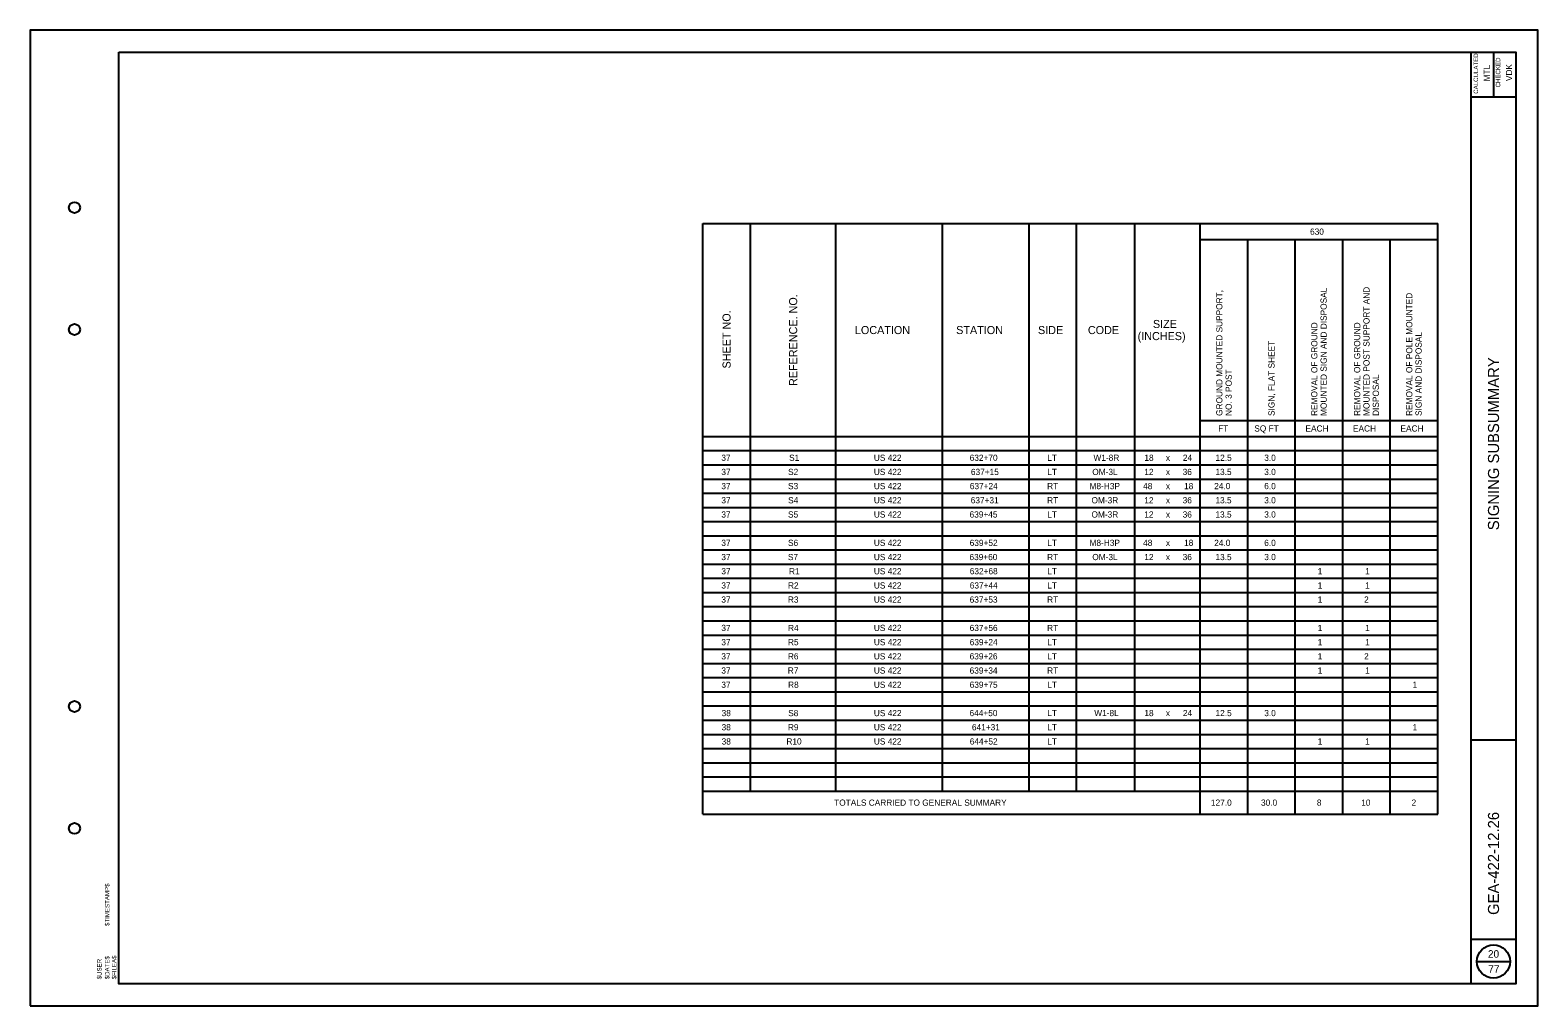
# Model space of a CAD drawing. Extents: x 0 to 34, y 0 to 22.
import ezdxf

# ---------------------------------------------------------------- set-up
doc = ezdxf.new("R2010")
doc.units = 0
for name, color, linetype in [('SH_Border', 7, 'Continuous'), ('SH_Cut_Line', 7, 'Continuous'), ('SH_Data', 7, 'Continuous'), ('SH_Text', 7, 'Continuous')]:
    doc.layers.add(name, color=color, linetype=linetype)

msp = doc.modelspace()

# ---------------------------------------------------------------- linework, layer by layer
at = {"layer": 'SH_Border'}
for p, q in [((32.5, 0.5), (32.5, 21.5)), ((33, 21.5), (33, 20.5)), ((32.5, 20.5), (33.5, 20.5)), ((32.5, 6), (33.5, 6)), ((32.5, 1.5), (33.5, 1.5))]:
    msp.add_line(p, q, dxfattribs=at)
msp.add_lwpolyline([(2, 21.5), (33.5, 21.5), (33.5, 0.5), (2, 0.5)], close=True, dxfattribs=at)
for centre in [(1, 18), (1, 15.25), (1, 6.75), (1, 4)]:
    msp.add_circle(centre, 0.125, dxfattribs=at)
at = {"layer": 'SH_Cut_Line'}
msp.add_lwpolyline([(0, 0), (34, 0), (34, 22), (0, 22)], close=True, dxfattribs=at)
at = {"layer": 'SH_Data'}
msp.add_line((32.625, 1), (33.375, 1), dxfattribs=at)
msp.add_circle((33, 1), 0.375, dxfattribs=at)
at = {"layer": 'SH_Text'}
for p, q in [((15.17, 17.637), (15.17, 17.637)), ((15.17, 17.637), (31.741, 17.637)), ((15.17, 4.323), (15.17, 17.637)), ((16.241, 4.842), (16.241, 17.637)), ((18.172, 4.842), (18.172, 17.637)), ((20.577, 4.842), (20.577, 17.637)), ((22.525, 4.842), (22.525, 17.637)), ((23.596, 4.842), (23.596, 17.637)), ((24.912, 4.842), (24.912, 17.637)), ((26.387, 4.323), (26.387, 17.637)), ((31.741, 4.323), (31.741, 17.637)), ((26.387, 17.277), (31.741, 17.277)), ((27.458, 4.323), (27.458, 17.277)), ((28.528, 4.323), (28.528, 17.277)), ((29.599, 4.323), (29.599, 17.277)), ((30.67, 4.323), (30.67, 17.277)), ((26.387, 13.199), (31.741, 13.199)), ((15.17, 12.839), (31.741, 12.839)), ((15.17, 12.519), (31.741, 12.519)), ((15.17, 12.199), (31.741, 12.199)), ((15.17, 11.879), (31.741, 11.879)), ((15.17, 11.56), (31.741, 11.56)), ((15.17, 11.24), (31.741, 11.24)), ((15.17, 10.92), (31.741, 10.92)), ((15.17, 10.6), (31.741, 10.6)), ((15.17, 10.28), (31.741, 10.28)), ((15.17, 9.96), (31.741, 9.96)), ((15.17, 9.64), (31.741, 9.64)), ((15.17, 9.32), (31.741, 9.32)), ((15.17, 9.001), (31.741, 9.001)), ((15.17, 8.681), (31.741, 8.681)), ((15.17, 8.361), (31.741, 8.361)), ((15.17, 8.041), (31.741, 8.041)), ((15.17, 7.721), (31.741, 7.721)), ((15.17, 7.401), (31.741, 7.401)), ((15.17, 7.081), (31.741, 7.081)), ((15.17, 6.762), (31.741, 6.762)), ((15.17, 6.442), (31.741, 6.442)), ((15.17, 6.122), (31.741, 6.122)), ((15.17, 5.802), (31.741, 5.802)), ((15.17, 5.482), (31.741, 5.482)), ((15.17, 5.162), (31.741, 5.162)), ((15.17, 4.842), (31.741, 4.842)), ((15.17, 4.323), (31.741, 4.323))]:
    msp.add_line(p, q, dxfattribs=at)

# ---------------------------------------------------------------- texts
at = {"layer": 'SH_Data'}
for s, height, rotation, p in [('CALCULATED', 0.1, 90, (32.652, 20.565)), ('MTL', 0.14, 90, (32.92, 20.844)), ('CHECKED', 0.1, 90, (33.152, 20.708)), ('VDK', 0.14, 90, (33.42, 20.851)), ('SIGNING SUBSUMMARY', 0.25, 90, (33.125, 10.724)), (' GEA-422-12.26 ', 0.25, 90, (33.125, 1.957)), ('$TIMESTAMP$', 0.1, 89.9931, (1.788, 1.8)), ('$USER', 0.1, 89.9931, (1.611, 0.598)), ('$DATE$', 0.1, 89.9931, (1.788, 0.598)), ('$FILEA$', 0.1, 89.9931, (1.944, 0.598))]:
    msp.add_text(s, height=height, rotation=rotation, dxfattribs=at).set_placement(p)
for s, p in [('20', (32.874, 1.085)), ('77', (32.882, 0.745))]:
    msp.add_text(s, height=0.17, dxfattribs=at).set_placement(p)
at = {"layer": 'SH_Text'}
for s, height, p in [('630', 0.14, (28.863, 17.387)), ('LOCATION', 0.182, (18.599, 15.147)), ('STATION', 0.182, (20.883, 15.147)), ('SIDE', 0.182, (22.728, 15.147)), ('CODE', 0.182, (23.853, 15.147)), ('SIZE', 0.182, (25.32, 15.284)), ('(INCHES)', 0.182, (24.975, 15.011)), ('FT', 0.14, (26.791, 12.949)), ('SQ FT', 0.14, (27.606, 12.949)), ('EACH', 0.14, (28.76, 12.949)), ('EACH', 0.14, (29.831, 12.949)), ('EACH', 0.14, (30.902, 12.949)), ('37', 0.14, (15.587, 12.289)), ('S1', 0.14, (17.115, 12.289)), ('US 422', 0.14, (19.026, 12.289)), ('632+70', 0.14, (21.187, 12.289)), ('LT', 0.14, (22.938, 12.289)), ('W1-8R', 0.14, (23.979, 12.289)), ('18', 0.14, (25.127, 12.289)), ('x', 0.14, (25.612, 12.289)), ('24', 0.14, (25.995, 12.289)), ('12.5', 0.14, (26.731, 12.289)), ('3.0', 0.14, (27.83, 12.289)), ('37', 0.14, (15.587, 11.969)), ('S2', 0.14, (17.092, 11.969)), ('US 422', 0.14, (19.026, 11.969)), ('637+15', 0.14, (21.215, 11.969)), ('LT', 0.14, (22.938, 11.969)), ('OM-3L', 0.14, (23.952, 11.969)), ('12', 0.14, (25.125, 11.969)), ('x', 0.14, (25.612, 11.969)), ('36', 0.14, (25.99, 11.969)), ('13.5', 0.14, (26.729, 11.969)), ('3.0', 0.14, (27.83, 11.969)), ('37', 0.14, (15.587, 11.65)), ('S3', 0.14, (17.091, 11.65)), ('US 422', 0.14, (19.026, 11.65)), ('637+24', 0.14, (21.19, 11.65)), ('RT', 0.14, (22.934, 11.65)), ('M8-H3P', 0.14, (23.89, 11.65)), ('48', 0.14, (25.099, 11.65)), ('x', 0.14, (25.612, 11.65)), ('18', 0.14, (26.022, 11.65)), ('24.0', 0.14, (26.701, 11.65)), ('6.0', 0.14, (27.83, 11.65)), ('37', 0.14, (15.587, 11.33)), ('S4', 0.14, (17.093, 11.33)), ('US 422', 0.14, (19.026, 11.33)), ('637+31', 0.14, (21.211, 11.33)), ('RT', 0.14, (22.934, 11.33)), ('OM-3R', 0.14, (23.934, 11.33)), ('12', 0.14, (25.125, 11.33)), ('x', 0.14, (25.612, 11.33)), ('36', 0.14, (25.99, 11.33)), ('13.5', 0.14, (26.729, 11.33)), ('3.0', 0.14, (27.83, 11.33)), ('37', 0.14, (15.587, 11.01)), ('S5', 0.14, (17.091, 11.01)), ('US 422', 0.14, (19.026, 11.01)), ('639+45', 0.14, (21.185, 11.01)), ('LT', 0.14, (22.938, 11.01)), ('OM-3R', 0.14, (23.934, 11.01)), ('12', 0.14, (25.125, 11.01)), ('x', 0.14, (25.612, 11.01)), ('36', 0.14, (25.99, 11.01)), ('13.5', 0.14, (26.729, 11.01)), ('3.0', 0.14, (27.83, 11.01)), ('37', 0.14, (15.587, 10.37)), ('S6', 0.14, (17.091, 10.37)), ('US 422', 0.14, (19.026, 10.37)), ('639+52', 0.14, (21.187, 10.37)), ('LT', 0.14, (22.938, 10.37)), ('M8-H3P', 0.14, (23.89, 10.37)), ('48', 0.14, (25.099, 10.37)), ('x', 0.14, (25.612, 10.37)), ('18', 0.14, (26.022, 10.37)), ('24.0', 0.14, (26.701, 10.37)), ('6.0', 0.14, (27.83, 10.37)), ('37', 0.14, (15.587, 10.05)), ('37', 0.14, (15.587, 9.73)), ('S7', 0.14, (17.088, 10.05)), ('R1', 0.14, (17.113, 9.73)), ('US 422', 0.14, (19.026, 10.05)), ('US 422', 0.14, (19.026, 9.73)), ('639+60', 0.14, (21.182, 10.05)), ('632+68', 0.14, (21.189, 9.73)), ('RT', 0.14, (22.934, 10.05)), ('LT', 0.14, (22.938, 9.73)), ('OM-3L', 0.14, (23.952, 10.05)), ('12', 0.14, (25.125, 10.05)), ('x', 0.14, (25.612, 10.05)), ('36', 0.14, (25.99, 10.05)), ('13.5', 0.14, (26.729, 10.05)), ('3.0', 0.14, (27.83, 10.05)), ('1', 0.14, (29.035, 9.73)), ('1', 0.14, (30.105, 9.73)), ('37', 0.14, (15.587, 9.41)), ('R2', 0.14, (17.09, 9.41)), ('US 422', 0.14, (19.026, 9.41)), ('637+44', 0.14, (21.189, 9.41)), ('LT', 0.14, (22.938, 9.41)), ('1', 0.14, (29.035, 9.41)), ('1', 0.14, (30.105, 9.41)), ('37', 0.14, (15.587, 9.091)), ('R3', 0.14, (17.088, 9.091)), ('US 422', 0.14, (19.026, 9.091)), ('637+53', 0.14, (21.187, 9.091)), ('RT', 0.14, (22.934, 9.091)), ('1', 0.14, (29.035, 9.091)), ('2', 0.14, (30.082, 9.091)), ('37', 0.14, (15.587, 8.451)), ('R4', 0.14, (17.091, 8.451)), ('US 422', 0.14, (19.026, 8.451)), ('637+56', 0.14, (21.187, 8.451)), ('RT', 0.14, (22.934, 8.451)), ('1', 0.14, (29.035, 8.451)), ('1', 0.14, (30.105, 8.451)), ('37', 0.14, (15.587, 8.131)), ('R5', 0.14, (17.089, 8.131)), ('US 422', 0.14, (19.026, 8.131)), ('639+24', 0.14, (21.188, 8.131)), ('LT', 0.14, (22.938, 8.131)), ('1', 0.14, (29.035, 8.131)), ('1', 0.14, (30.105, 8.131)), ('37', 0.14, (15.587, 7.811)), ('R6', 0.14, (17.088, 7.811)), ('US 422', 0.14, (19.026, 7.811)), ('639+26', 0.14, (21.186, 7.811)), ('LT', 0.14, (22.938, 7.811)), ('1', 0.14, (29.035, 7.811)), ('2', 0.14, (30.082, 7.811)), ('37', 0.14, (15.587, 7.491)), ('R7', 0.14, (17.086, 7.491)), ('US 422', 0.14, (19.026, 7.491)), ('639+34', 0.14, (21.186, 7.491)), ('RT', 0.14, (22.934, 7.491)), ('1', 0.14, (29.035, 7.491)), ('1', 0.14, (30.105, 7.491)), ('37', 0.14, (15.587, 7.171)), ('R8', 0.14, (17.092, 7.171)), ('US 422', 0.14, (19.026, 7.171)), ('639+75', 0.14, (21.187, 7.171)), ('LT', 0.14, (22.938, 7.171)), ('1', 0.14, (31.176, 7.171)), ('38', 0.14, (15.593, 6.532)), ('S8', 0.14, (17.094, 6.532)), ('US 422', 0.14, (19.026, 6.532)), ('644+50', 0.14, (21.184, 6.532)), ('LT', 0.14, (22.938, 6.532)), ('W1-8L', 0.14, (23.997, 6.532)), ('18', 0.14, (25.127, 6.532)), ('x', 0.14, (25.612, 6.532)), ('24', 0.14, (25.995, 6.532)), ('12.5', 0.14, (26.731, 6.532)), ('3.0', 0.14, (27.83, 6.532)), ('38', 0.14, (15.593, 6.212)), ('R9', 0.14, (17.089, 6.212)), ('US 422', 0.14, (19.026, 6.212)), ('641+31', 0.14, (21.238, 6.212)), ('LT', 0.14, (22.938, 6.212)), ('1', 0.14, (31.176, 6.212)), ('38', 0.14, (15.593, 5.892)), ('R10', 0.14, (17.054, 5.892)), ('US 422', 0.14, (19.026, 5.892)), ('644+52', 0.14, (21.188, 5.892)), ('LT', 0.14, (22.938, 5.892)), ('1', 0.14, (29.035, 5.892)), ('1', 0.14, (30.105, 5.892)), ('TOTALS CARRIED TO GENERAL SUMMARY', 0.14, (18.131, 4.512)), ('127.0', 0.14, (26.628, 4.512)), ('30.0', 0.14, (27.757, 4.512)), ('8', 0.14, (29.017, 4.512)), ('10', 0.14, (30.017, 4.512)), ('2', 0.14, (31.153, 4.512))]:
    msp.add_text(s, height=height, dxfattribs=at).set_placement(p)
for s, height, p in [('REFERENCE. NO.', 0.182, (17.297, 13.976)), ('GROUND MOUNTED SUPPORT,', 0.14, (26.887, 13.301)), ('MOUNTED SIGN AND DISPOSAL', 0.14, (29.239, 13.301)), ('MOUNTED POST SUPPORT AND', 0.14, (30.205, 13.301)), ('REMOVAL OF POLE MOUNTED', 0.14, (31.17, 13.301)), ('SHEET NO.', 0.182, (15.796, 14.371)), ('REMOVAL OF GROUND', 0.14, (29.029, 13.301)), ('REMOVAL OF GROUND', 0.14, (29.995, 13.301)), ('SIGN, FLAT SHEET', 0.14, (28.063, 13.301)), ('SIGN AND DISPOSAL', 0.14, (31.38, 13.301)), ('NO. 3 POST', 0.14, (27.097, 13.301)), ('DISPOSAL', 0.14, (30.415, 13.301))]:
    msp.add_text(s, height=height, rotation=90, dxfattribs=at).set_placement(p)

doc.saveas('drawing.dxf')
